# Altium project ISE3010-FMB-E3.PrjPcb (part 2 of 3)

## Sheet FPGA Power.SchDoc: FPGA Power
size 431 x 279 mm; Date: Not shown in title block; ApprovedBy: Not shown in title block; CheckedBy: Not shown in title block; Author: Not shown in title block; CompanyName: Not shown in title block; Engineer: Not shown in title block; Organization: Not shown in title block; Address1: Not shown in title block; Address2: Not shown in title block; Address3: Not shown in title block; Address4: Not shown in title block; DocumentNumber: 6; Revision: Use project parameter SCH_Rev; SheetNumber: 6; SheetTotal: 9; PageSetup: Record=PageOptions|CenterHorizontal=True|CenterVertical=True|PrintScale=1.00|XCorrection=1.00|YCorrection=1.00|PrintKind=0|BorderSize=5000000|LeftOffset=0|BottomOffset=0|Orientation=2|PaperLength=1000|PaperWidth=1000|Scale=100|PaperSource=15|PrintQuality=600|MediaType=1|DitherType=10|PaperKind=Letter|PrintScaleMode=1
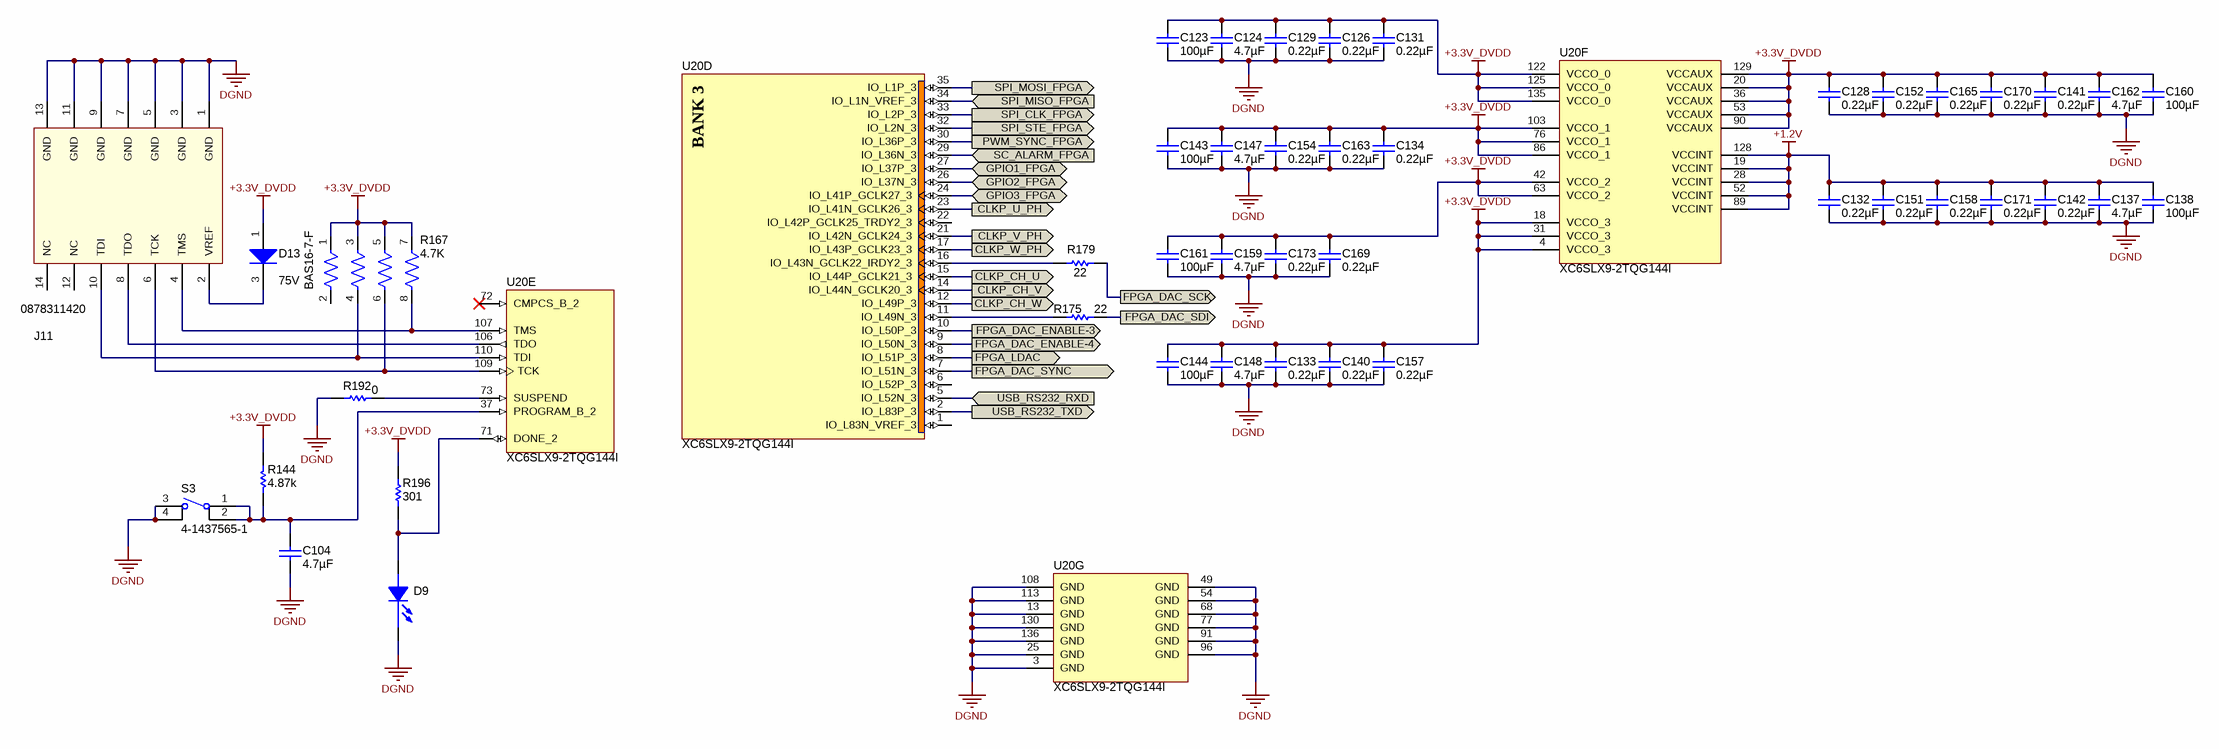
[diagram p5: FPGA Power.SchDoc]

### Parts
C104  ValueDisplayed: 4.7µF  [0603]  (hidden comment: C0603C475K9PACTU)
C123  ValueDisplayed: 100µF  [1206]  (hidden comment: GRM31CR60J107ME39L)
C124  ValueDisplayed: 4.7µF  [0603]  (hidden comment: C0603C475K9PACTU)
C126  ValueDisplayed: 0.22µF  [0603]  (hidden comment: GRM188R70J224KA88D)
C128  ValueDisplayed: 0.22µF  [0603]  (hidden comment: GRM188R70J224KA88D)
C129  ValueDisplayed: 0.22µF  [0603]  (hidden comment: GRM188R70J224KA88D)
C131  ValueDisplayed: 0.22µF  [0603]  (hidden comment: GRM188R70J224KA88D)
C132  ValueDisplayed: 0.22µF  [0603]  (hidden comment: GRM188R70J224KA88D)
C133  ValueDisplayed: 0.22µF  [0603]  (hidden comment: GRM188R70J224KA88D)
C134  ValueDisplayed: 0.22µF  [0603]  (hidden comment: GRM188R70J224KA88D)
C137  ValueDisplayed: 4.7µF  [0603]  (hidden comment: C0603C475K9PACTU)
C138  ValueDisplayed: 100µF  [1206]  (hidden comment: GRM31CR60J107ME39L)
C140  ValueDisplayed: 0.22µF  [0603]  (hidden comment: GRM188R70J224KA88D)
C141  ValueDisplayed: 0.22µF  [0603]  (hidden comment: GRM188R70J224KA88D)
C142  ValueDisplayed: 0.22µF  [0603]  (hidden comment: GRM188R70J224KA88D)
C143  ValueDisplayed: 100µF  [1206]  (hidden comment: GRM31CR60J107ME39L)
C144  ValueDisplayed: 100µF  [1206]  (hidden comment: GRM31CR60J107ME39L)
C147  ValueDisplayed: 4.7µF  [0603]  (hidden comment: C0603C475K9PACTU)
C148  ValueDisplayed: 4.7µF  [0603]  (hidden comment: C0603C475K9PACTU)
C151  ValueDisplayed: 0.22µF  [0603]  (hidden comment: GRM188R70J224KA88D)
C152  ValueDisplayed: 0.22µF  [0603]  (hidden comment: GRM188R70J224KA88D)
C154  ValueDisplayed: 0.22µF  [0603]  (hidden comment: GRM188R70J224KA88D)
C157  ValueDisplayed: 0.22µF  [0603]  (hidden comment: GRM188R70J224KA88D)
C158  ValueDisplayed: 0.22µF  [0603]  (hidden comment: GRM188R70J224KA88D)
C159  ValueDisplayed: 4.7µF  [0603]  (hidden comment: C0603C475K9PACTU)
C160  ValueDisplayed: 100µF  [1206]  (hidden comment: GRM31CR60J107ME39L)
C161  ValueDisplayed: 100µF  [1206]  (hidden comment: GRM31CR60J107ME39L)
C162  ValueDisplayed: 4.7µF  [0603]  (hidden comment: C0603C475K9PACTU)
C163  ValueDisplayed: 0.22µF  [0603]  (hidden comment: GRM188R70J224KA88D)
C165  ValueDisplayed: 0.22µF  [0603]  (hidden comment: GRM188R70J224KA88D)
C169  ValueDisplayed: 0.22µF  [0603]  (hidden comment: GRM188R70J224KA88D)
C170  ValueDisplayed: 0.22µF  [0603]  (hidden comment: GRM188R70J224KA88D)
C171  ValueDisplayed: 0.22µF  [0603]  (hidden comment: GRM188R70J224KA88D)
C173  ValueDisplayed: 0.22µF  [0603]  (hidden comment: GRM188R70J224KA88D)
D9  (no value)  [LED0603AA]
D13  BAS16-7-F  value 75V  [SOT-23]
J11  0878311420  [CONN_0878311420]
R144  value 4.87k  [0603]  (hidden comment: CRCW06034K87FKEA)
R167  4.7K  [R-ACAS_0612]
R175  value 22  [0402]  (hidden comment: CRCW040222R0JNED)
R179  value 22  [0402]  (hidden comment: CRCW040222R0JNED)
R192  value 0  [0603]  (hidden comment: CRCW06030000Z0EA)
R196  value 301  [0603]  (hidden comment: RT0603DRE07301RL)
S3  4-1437565-1  [SW_FSM4JSMA]
U20  XC6SLX9-2TQG144I  [TQG144_N]  (parts D,E,F,G of 7)

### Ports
CLKP_CH_U (out), CLKP_CH_V (out), CLKP_CH_W (out), CLKP_U_PH (out), CLKP_V_PH (out), CLKP_W_PH (out), FPGA_DAC_ENABLE-3 (out), FPGA_DAC_ENABLE-4 (out), FPGA_DAC_SCK (out), FPGA_DAC_SDI (out), FPGA_DAC_SYNC (out), FPGA_LDAC (out), GPIO1_FPGA (bidir), GPIO2_FPGA (bidir), GPIO3_FPGA (bidir), PWM_SYNC_FPGA, SC_ALARM_FPGA (in), SPI_CLK_FPGA, SPI_MISO_FPGA (in), SPI_MOSI_FPGA, SPI_STE_FPGA, USB_RS232_RXD (in), USB_RS232_TXD (out)

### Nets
+1.2V: C132.2 C137.1 C138.1 C142.2 C151.2 C158.2 C171.2 U20.19(VCCINT) U20.28(VCCINT) U20.52(VCCINT) U20.89(VCCINT) U20.128(VCCINT)
+3.3V_DVDD: C123.1 C124.1 C126.2 C128.2 C129.2 C131.2 C133.2 C134.2 C140.2 C141.2 C143.1 C144.1 C147.1 C148.1 C152.2 C154.2 C157.2 C159.1 C160.1 C161.1 C162.1 C163.2 C165.2 C169.2 C170.2 C173.2 D13.1(A) R144.2 R167.1 R167.3 R167.5 R167.7 R196.2 U20.4(VCCO_3) U20.18(VCCO_3) U20.20(VCCAUX) U20.31(VCCO_3) U20.36(VCCAUX) U20.42(VCCO_2) U20.53(VCCAUX) U20.63(VCCO_2) U20.76(VCCO_1) U20.86(VCCO_1) U20.90(VCCAUX) U20.103(VCCO_1) U20.122(VCCO_0) U20.125(VCCO_0) U20.129(VCCAUX) U20.135(VCCO_0)
DGND: C104.1 C123.2 C124.2 C126.1 C128.1 C129.1 C131.1 C132.1 C133.1 C134.1 C137.2 C138.2 C140.1 C141.1 C142.1 C143.2 C144.2 C147.2 C148.2 C151.1 C152.1 C154.1 C157.1 C158.1 C159.2 C160.2 C161.2 C162.2 C163.1 C165.1 C169.1 C170.1 C171.1 C173.1 D9.1(C) J11.1(GND) J11.3(GND) J11.5(GND) J11.7(GND) J11.9(GND) J11.11(GND) J11.13(GND) R192.1 S3.3 S3.4 U20.3(GND) U20.13(GND) U20.25(GND) U20.49(GND) U20.54(GND) U20.68(GND) U20.77(GND) U20.91(GND) U20.96(GND) U20.108(GND) U20.113(GND) U20.130(GND) U20.136(GND)
CLKP_CH_U: U20.15(IO_L44P_GCLK21_3) ; port CLKP_CH_U
CLKP_CH_V: U20.14(IO_L44N_GCLK20_3) ; port CLKP_CH_V
CLKP_CH_W: U20.12(IO_L49P_3) ; port CLKP_CH_W
CLKP_U_PH: U20.23(IO_L41N_GCLK26_3) ; port CLKP_U_PH
CLKP_V_PH: U20.21(IO_L42N_GCLK24_3) ; port CLKP_V_PH
CLKP_W_PH: U20.17(IO_L43P_GCLK23_3) ; port CLKP_W_PH
FPGA_DAC_ENABLE-3: U20.10(IO_L50P_3) ; port FPGA_DAC_ENABLE-3
FPGA_DAC_ENABLE-4: U20.9(IO_L50N_3) ; port FPGA_DAC_ENABLE-4
FPGA_DAC_SCK: R179.1 ; port FPGA_DAC_SCK
FPGA_DAC_SDI: R175.1 ; port FPGA_DAC_SDI
FPGA_DAC_SYNC: U20.7(IO_L51N_3) ; port FPGA_DAC_SYNC
FPGA_LDAC: U20.8(IO_L51P_3) ; port FPGA_LDAC
GPIO1_FPGA: U20.27(IO_L37P_3) ; port GPIO1_FPGA
GPIO2_FPGA: U20.26(IO_L37N_3) ; port GPIO2_FPGA
GPIO3_FPGA: U20.24(IO_L41P_GCLK27_3) ; port GPIO3_FPGA
PWM_SYNC_FPGA: U20.30(IO_L36P_3) ; port PWM_SYNC_FPGA
SC_ALARM_FPGA: U20.29(IO_L36N_3) ; port SC_ALARM_FPGA
SPI_CLK_FPGA: U20.33(IO_L2P_3) ; port SPI_CLK_FPGA
SPI_MISO_FPGA: U20.34(IO_L1N_VREF_3) ; port SPI_MISO_FPGA
SPI_MOSI_FPGA: U20.35(IO_L1P_3) ; port SPI_MOSI_FPGA
SPI_STE_FPGA: U20.32(IO_L2N_3) ; port SPI_STE_FPGA
USB_RS232_RXD: U20.5(IO_L52N_3) ; port USB_RS232_RXD
USB_RS232_TXD: U20.2(IO_L83P_3) ; port USB_RS232_TXD
NetC104_2: C104.2 R144.1 S3.1 S3.2 U20.37(PROGRAM_B_2)
NetD9_2: D9.2(A) R196.1 U20.71(DONE_2)
NetD13_3: D13.3(K) J11.2(VREF)
NetJ11_4: J11.4(TMS) R167.8 U20.107(TMS)
NetJ11_6: J11.6(TCK) R167.6 U20.109(TCK)
NetJ11_8: J11.8(TDO) U20.106(TDO)
NetJ11_10: J11.10(TDI) R167.4 U20.110(TDI)
NetR175_2: R175.2 U20.11(IO_L49N_3)
NetR179_2: R179.2 U20.16(IO_L43N_GCLK22_IRDY2_3)
NetR192_2: R192.2 U20.73(SUSPEND)

Not connected (* = marked no-connect by the designer): J11 12(NC) 14(NC); R167 2; U20 1(IO_L83N_VREF_3) 6(IO_L52P_3) 22(IO_L42P_GCLK25_TRDY2_3) 72(CMPCS_B_2)*

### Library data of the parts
C104 C124 C137 C147 C148 C159 C162 = C0603C475K9PACTU: CAP, CERM, 4.7uF, 6.3V, +/-10%, X5R, 0603; Manufacturer: Kemet; Polarized: N; CompType: Capacitor; U/M: EA; Cap_F: 0.0000047; Tolerance_%: 10; ESR_Ohm: 0.006; Value1: 0.006 ohm; VDC_V: 6.3; IRMS_A: 7.24; TaMin_C: -55; TaMax_C: 85
C123 C138 C143 C144 C160 C161 = GRM31CR60J107ME39L: CAP, CERM, 100uF, 6.3V, +/-20%, X5R, 1206; Manufacturer: MuRata; Polarized: N; CompType: Capacitor; U/M: EA; Cap_F: 0.0001; Tolerance_%: 20; ESR_Ohm: 0.003; Value1: 0.003 ohm; VDC_V: 6.3; TaMin_C: -55; TaMax_C: 85
C126 C128 C129 C131-C134 C140-C142 C151 C152 C154 C157 C158 C163 C165 C169-C171 C173 = GRM188R70J224KA88D: CAP, CERM, 0.22uF, 6.3V, +/-10%, X7R, 0603; Manufacturer: MuRata; Polarized: N; CompType: Capacitor; U/M: EA; Cap_F: 0.00000022; Tolerance_%: 10; Value1: Unknown; VDC_V: 6.3; TaMin_C: -55; TaMax_C: 125
D9 = LED_LG L29K-G2J1-24-Z: LED SmartLED Green 570NM; Manufacturer: OSRAM; SymbolCreator: x0120606
D13 = BAS16-7-F: Diode, Ultrafast, 75V, 0.3A, SOT-23; Manufacturer: Diodes Inc.; U/M: EA; Vf_V: 1.125; Value2: 1.125V; Io_A: 0.3; Vr_V: 75
J11 = CON_0878311420: Cnnector Header 14Pos 2mm Vert Gold; Manufacturer: Molex Inc; SymbolCreator: x0120606
R144 = CRCW06034K87FKEA: RES, 4.87k ohm, 1%, 0.1W, 0603; Manufacturer: Vishay-Dale; CompType: Resistor; Res_ohm: 4870; Value_Code: 4k87; Tolerance_%: 1; Power_W: 0.1; VDC_V: 75; TempCo: 100 ppm/C; EIA_Code: E96; U/M: EA
R167 = R-ACAS0612_SERIES: Resistor, Chip Array, 4.7K OHM 4 RES 0612; Manufacturer: Vishay; PartNumber: ACASA470124701P100; Area: 22308
R175 R179 = CRCW040222R0JNED: RES, 22 ohm, 5%, 0.063W, 0402; Manufacturer: Vishay-Dale; CompType: Resistor; Value_Code: 22R0; Tolerance_%: 5; Power_W: 0.063; VDC_V: 50; TempCo: 200 ppm/C; EIA_Code: E24; U/M: EA
R192 = CRCW06030000Z0EA: RES, 0 ohm, 5%, 0.1W, 0603; Manufacturer: Vishay-Dale; CompType: Resistor; Value_Code: 0000; Tolerance_%: 5; Power_W: 0.1; VDC_V: 75; TempCo: 200 ppm/C; EIA_Code: E24; U/M: EA
R196 = RT0603DRE07301RL: RES, 301 ohm, 0.5%, 0.1W, 0603; Manufacturer: Yageo America; CompType: Resistor; Value_Code: 301R; Tolerance_%: 0.5; Power_W: 0.1; VDC_V: 75; TempCo: 50 ppm/C; EIA_Code: E192; U/M: EA
S3 = 4-1437565-1: Switch, Tactile, SPST-NO, 0.05A, 12V, SMT; Manufacturer: TE Connectivity; SymbolCreator: a0412235; VDC_V: 12; SwitchFunction: Off-Mom; PositionCount: 1; CurrentRating_mA: 50
U20 = XC6SLX9-2TQG144I: IC FPGA SPARTAN, 102 I/O, 144TQFP; Manufacturer: Xilinx; SymbolCreator: x0120606

## Sheet FPGA CLOCK_USB.SchDoc: FPGA CLOCK_USB
size 431 x 279 mm; Date: Not shown in title block; ApprovedBy: Not shown in title block; CheckedBy: Not shown in title block; Author: Not shown in title block; CompanyName: Not shown in title block; Engineer: Not shown in title block; Organization: Not shown in title block; Address1: Not shown in title block; Address2: Not shown in title block; Address3: Not shown in title block; Address4: Not shown in title block; DocumentNumber: 7; Revision: Use project parameter SCH_Rev; SheetNumber: 7; SheetTotal: 9; PageSetup: Record=PageOptions|CenterHorizontal=True|CenterVertical=True|PrintScale=0.62|XCorrection=1.00|YCorrection=1.00|PrintKind=0|BorderSize=5000000|LeftOffset=0|BottomOffset=0|Orientation=2|PaperLength=1000|PaperWidth=1000|Scale=100|PaperSource=15|PrintQuality=600|MediaType=1|DitherType=10|PaperKind=Letter|PrintScaleMode=1
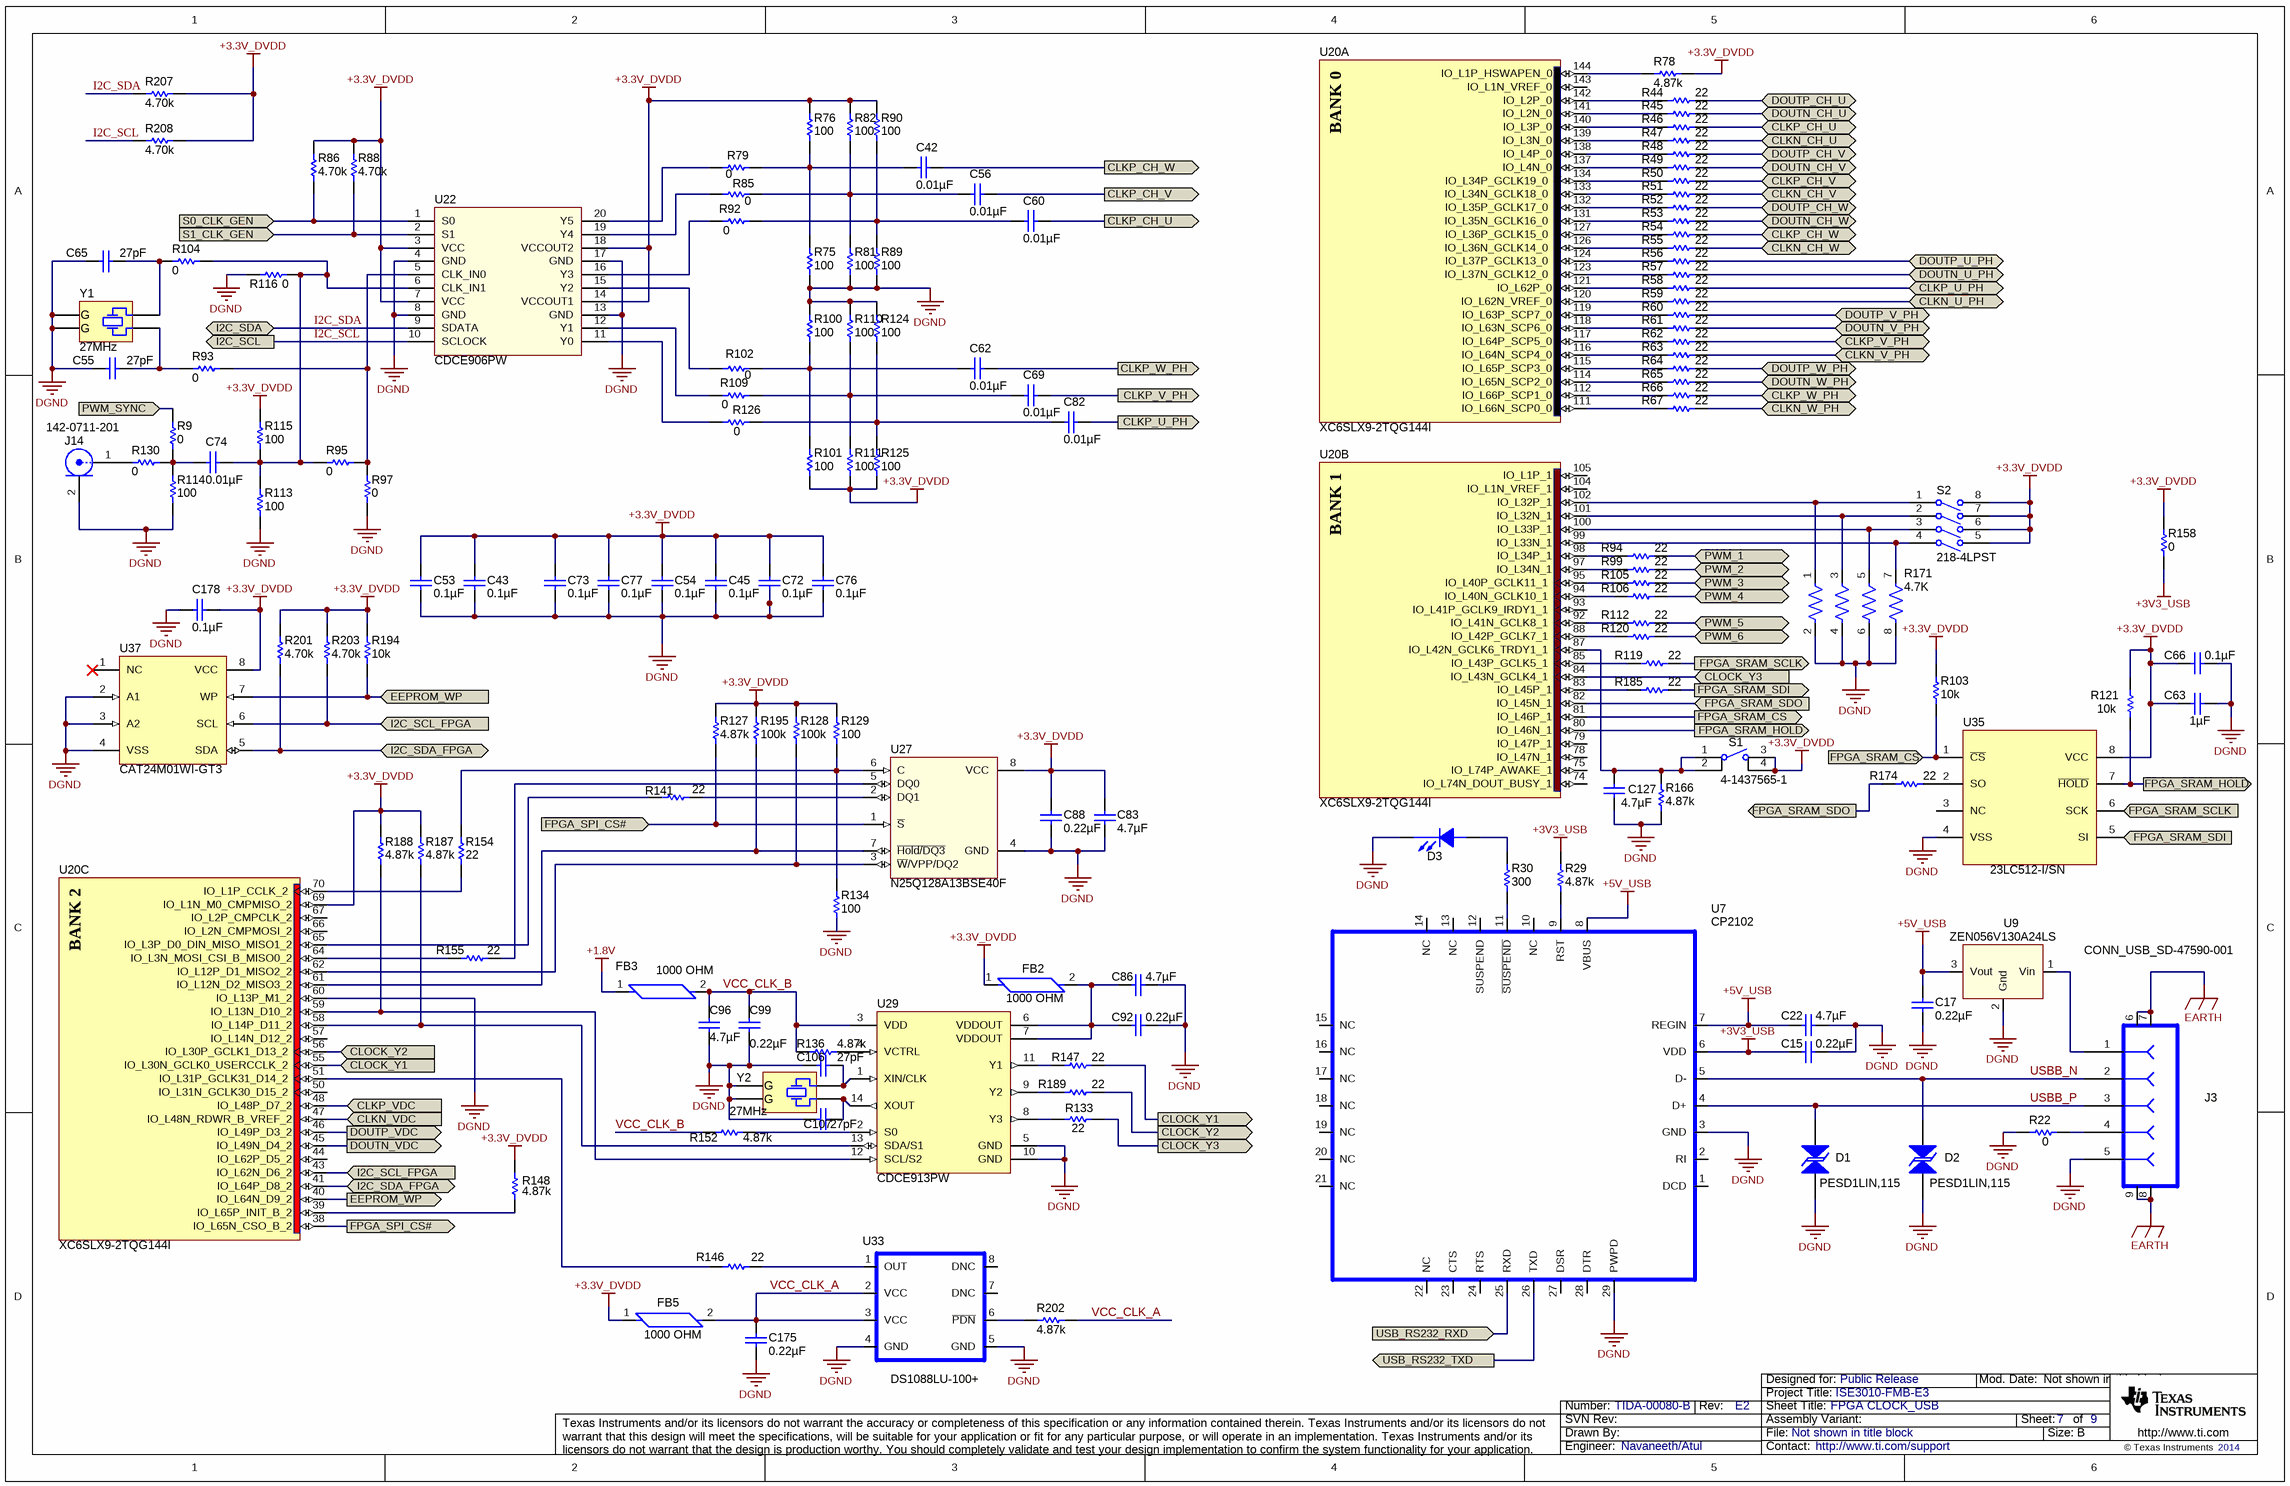
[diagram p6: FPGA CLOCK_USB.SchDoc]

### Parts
C15  ValueDisplayed: 0.22µF  [0603]  (hidden comment: GRM188R70J224KA88D)
C17  ValueDisplayed: 0.22µF  [0603]  (hidden comment: GRM188R70J224KA88D)
C22  ValueDisplayed: 4.7µF  [0603]  (hidden comment: C0603C475K9PACTU)
C42  ValueDisplayed: 0.01µF  [0603]  (hidden comment: 06031C103KAT2A)
C43  ValueDisplayed: 0.1µF  [0603]  (hidden comment: 06033C104JAT2A)
C45  ValueDisplayed: 0.1µF  [0603]  (hidden comment: 06033C104JAT2A)
C53  ValueDisplayed: 0.1µF  [0603]  (hidden comment: 06033C104JAT2A)
C54  ValueDisplayed: 0.1µF  [0603]  (hidden comment: 06033C104JAT2A)
C55  ValueDisplayed: 27pF  [0603]  (hidden comment: 06035A270JAT2A)
C56  ValueDisplayed: 0.01µF  [0603]  (hidden comment: 06031C103KAT2A)
C60  ValueDisplayed: 0.01µF  [0603]  (hidden comment: 06031C103KAT2A)
C62  ValueDisplayed: 0.01µF  [0603]  (hidden comment: 06031C103KAT2A)
C63  ValueDisplayed: 1µF  [0603]  (hidden comment: C1608X5R1C105K)
C65  ValueDisplayed: 27pF  [0603]  (hidden comment: 06035A270JAT2A)
C66  ValueDisplayed: 0.1µF  [0603]  (hidden comment: 0603YC104JAT2A)
C69  ValueDisplayed: 0.01µF  [0603]  (hidden comment: 06031C103KAT2A)
C72  ValueDisplayed: 0.1µF  [0603]  (hidden comment: 06033C104JAT2A)
C73  ValueDisplayed: 0.1µF  [0603]  (hidden comment: 06033C104JAT2A)
C74  ValueDisplayed: 0.01µF  [0603]  (hidden comment: 06031C103KAT2A)
C76  ValueDisplayed: 0.1µF  [0603]  (hidden comment: 06033C104JAT2A)
C77  ValueDisplayed: 0.1µF  [0603]  (hidden comment: 06033C104JAT2A)
C82  ValueDisplayed: 0.01µF  [0603]  (hidden comment: 06031C103KAT2A)
C83  ValueDisplayed: 4.7µF  [0603]  (hidden comment: C0603C475K9PACTU)
C86  ValueDisplayed: 4.7µF  [0603]  (hidden comment: C0603C475K9PACTU)
C88  ValueDisplayed: 0.22µF  [0603]  (hidden comment: GRM188R70J224KA88D)
C92  ValueDisplayed: 0.22µF  [0603]  (hidden comment: GRM188R70J224KA88D)
C96  ValueDisplayed: 4.7µF  [0603]  (hidden comment: C0603C475K9PACTU)
C99  ValueDisplayed: 0.22µF  [0603]  (hidden comment: GRM188R70J224KA88D)
C106  ValueDisplayed: 27pF  [0603]  (hidden comment: 06035A270JAT2A)
C107  ValueDisplayed: 27pF  [0603]  (hidden comment: 06035A270JAT2A)
C127  ValueDisplayed: 4.7µF  [0603]  (hidden comment: C0603C475K9PACTU)
C175  ValueDisplayed: 0.22µF  [0603]  (hidden comment: GRM188R70J224KA88D)
C178  ValueDisplayed: 0.1µF  [0603]  (hidden comment: 0603YC104JAT2A)
D1  PESD1LIN,115  [sod-323]
D2  PESD1LIN,115  [sod-323]
D3  (no value)  [LED0603AA]
FB2  value 1000 OHM  [FB0603]
FB3  value 1000 OHM  [FB0603]
FB5  value 1000 OHM  [FB0603]
J3  CONN_USB_SD-47590-001  [USB-SD-47590-001]
J14  142-0711-201  [142-0711-201]
R9  value 0  [0603]  (hidden comment: CRCW06030000Z0EA)
R22  value 0  [0603]  (hidden comment: CRCW06030000Z0EA)
R29  value 4.87k  [0603]  (hidden comment: CRCW06034K87FKEA)
R30  value 300  [0603]  (hidden comment: CRCW0603300RJNEA)
R44  value 22  [0402]  (hidden comment: CRCW040222R0JNED)
R45  value 22  [0402]  (hidden comment: CRCW040222R0JNED)
R46  value 22  [0402]  (hidden comment: CRCW040222R0JNED)
R47  value 22  [0402]  (hidden comment: CRCW040222R0JNED)
R48  value 22  [0402]  (hidden comment: CRCW040222R0JNED)
R49  value 22  [0402]  (hidden comment: CRCW040222R0JNED)
R50  value 22  [0402]  (hidden comment: CRCW040222R0JNED)
R51  value 22  [0402]  (hidden comment: CRCW040222R0JNED)
R52  value 22  [0402]  (hidden comment: CRCW040222R0JNED)
R53  value 22  [0402]  (hidden comment: CRCW040222R0JNED)
R54  value 22  [0402]  (hidden comment: CRCW040222R0JNED)
R55  value 22  [0402]  (hidden comment: CRCW040222R0JNED)
R56  value 22  [0402]  (hidden comment: CRCW040222R0JNED)
R57  value 22  [0402]  (hidden comment: CRCW040222R0JNED)
R58  value 22  [0402]  (hidden comment: CRCW040222R0JNED)
R59  value 22  [0402]  (hidden comment: CRCW040222R0JNED)
R60  value 22  [0402]  (hidden comment: CRCW040222R0JNED)
R61  value 22  [0402]  (hidden comment: CRCW040222R0JNED)
R62  value 22  [0402]  (hidden comment: CRCW040222R0JNED)
R63  value 22  [0402]  (hidden comment: CRCW040222R0JNED)
R64  value 22  [0402]  (hidden comment: CRCW040222R0JNED)
R65  value 22  [0402]  (hidden comment: CRCW040222R0JNED)
R66  value 22  [0402]  (hidden comment: CRCW040222R0JNED)
R67  value 22  [0402]  (hidden comment: CRCW040222R0JNED)
R75  value 100  [0603]  (hidden comment: CRCW0603100RJNEA)
R76  value 100  [0603]  (hidden comment: CRCW0603100RJNEA)
R78  value 4.87k  [0603]  (hidden comment: CRCW06034K87FKEA)
R79  value 0  [0603]  (hidden comment: CRCW06030000Z0EA)
R81  value 100  [0603]  (hidden comment: CRCW0603100RJNEA)
R82  value 100  [0603]  (hidden comment: CRCW0603100RJNEA)
R85  value 0  [0603]  (hidden comment: CRCW06030000Z0EA)
R86  value 4.70k  [0603]  (hidden comment: RC0603FR-074K7L)
R88  value 4.70k  [0603]  (hidden comment: RC0603FR-074K7L)
R89  value 100  [0603]  (hidden comment: CRCW0603100RJNEA)
R90  value 100  [0603]  (hidden comment: CRCW0603100RJNEA)
R92  value 0  [0603]  (hidden comment: CRCW06030000Z0EA)
R93  value 0  [0402]  (hidden comment: CRCW04020000Z0ED)
R94  value 22  [0402]  (hidden comment: CRCW040222R0JNED)
R95  value 0  [0402]  (hidden comment: CRCW04020000Z0ED)
R97  value 0  [0402]  (hidden comment: CRCW04020000Z0ED)
R99  value 22  [0402]  (hidden comment: CRCW040222R0JNED)
R100  value 100  [0603]  (hidden comment: CRCW0603100RJNEA)
R101  value 100  [0603]  (hidden comment: CRCW0603100RJNEA)
R102  value 0  [0603]  (hidden comment: CRCW06030000Z0EA)
R103  value 10k  [0603]  (hidden comment: CRCW060310K0JNEA)
R104  value 0  [0402]  (hidden comment: CRCW04020000Z0ED)
R105  value 22  [0402]  (hidden comment: CRCW040222R0JNED)
R106  value 22  [0402]  (hidden comment: CRCW040222R0JNED)
R109  value 0  [0603]  (hidden comment: CRCW06030000Z0EA)
R110  value 100  [0603]  (hidden comment: CRCW0603100RJNEA)
R111  value 100  [0603]  (hidden comment: CRCW0603100RJNEA)
R112  value 22  [0402]  (hidden comment: CRCW040222R0JNED)
R113  value 100  [0603]  (hidden comment: CRCW0603100RJNEA)
R114  value 100  [0603]  (hidden comment: CRCW0603100RJNEA)
R115  value 100  [0603]  (hidden comment: CRCW0603100RJNEA)
R116  value 0  [0402]  (hidden comment: CRCW04020000Z0ED)
R119  value 22  [0402]  (hidden comment: CRCW040222R0JNED)
R120  value 22  [0402]  (hidden comment: CRCW040222R0JNED)
R121  value 10k  [0603]  (hidden comment: CRCW060310K0JNEA)
R124  value 100  [0603]  (hidden comment: CRCW0603100RJNEA)
R125  value 100  [0603]  (hidden comment: CRCW0603100RJNEA)
R126  value 0  [0603]  (hidden comment: CRCW06030000Z0EA)
R127  value 4.87k  [0603]  (hidden comment: CRCW06034K87FKEA)
R128  value 100k  [0603]  (hidden comment: CRCW0603100KFKEA)
R129  value 100  [0603]  (hidden comment: CRCW0603100RJNEA)
R130  value 0  [0603]  (hidden comment: CRCW06030000Z0EA)
R133  value 22  [0402]  (hidden comment: CRCW040222R0JNED)
R134  value 100  [0603]  (hidden comment: CRCW0603100RJNEA)
R136  value 4.87k  [0603]  (hidden comment: CRCW06034K87FKEA)
R141  value 22  [0402]  (hidden comment: CRCW040222R0JNED)
R146  value 22  [0402]  (hidden comment: CRCW040222R0JNED)
R147  value 22  [0402]  (hidden comment: CRCW040222R0JNED)
R148  value 4.87k  [0603]  (hidden comment: CRCW06034K87FKEA)
R152  value 4.87k  [0603]  (hidden comment: CRCW06034K87FKEA)
R154  value 22  [0402]  (hidden comment: CRCW040222R0JNED)
R155  value 22  [0402]  (hidden comment: CRCW040222R0JNED)
R158  value 0  [0603]  (hidden comment: CRCW06030000Z0EA)
R166  value 4.87k  [0603]  (hidden comment: CRCW06034K87FKEA)
R171  4.7K  [R-ACAS_0612]
R174  value 22  [0402]  (hidden comment: CRCW040222R0JNED)
R185  value 22  [0402]  (hidden comment: CRCW040222R0JNED)
R187  value 4.87k  [0603]  (hidden comment: CRCW06034K87FKEA)
R188  value 4.87k  [0603]  (hidden comment: CRCW06034K87FKEA)
R189  value 22  [0402]  (hidden comment: CRCW040222R0JNED)
R194  value 10k  [0603]  (hidden comment: RC0603JR-0710KL)
R195  value 100k  [0603]  (hidden comment: CRCW0603100KFKEA)
R201  value 4.70k  [0603]  (hidden comment: RC0603FR-074K7L)
R202  value 4.87k  [0603]  (hidden comment: CRCW06034K87FKEA)
R203  value 4.70k  [0603]  (hidden comment: RC0603FR-074K7L)
R207  value 4.70k  [0603]  (hidden comment: RC0603FR-074K7L)
R208  value 4.70k  [0603]  (hidden comment: RC0603FR-074K7L)
S1  4-1437565-1  [SW_FSM4JSMA]
S2  218-4LPST  [SW_218-4LPST]
U7  CP2102  [QFN28[RHD]]
U9  ZEN056V130A24LS  [POLYZEN 4 x 4 SMD]
U20  XC6SLX9-2TQG144I  [TQG144_N]  (parts A,B,C of 7)
U22  CDCE906PW  [PW0020A_L]
U27  N25Q128A13BSE40F  [SO8W]
U29  CDCE913PW  [PW0014A_N]
U33  DS1088LU-100+  [DGK8]
U35  23LC512-I/SN  [SO8]
U37  CAT24M01WI-GT3  [SO8]
Y1  Frequency: 27MHz  [XTAL_TXC-7B]  (hidden comment: 7B-27.000MEEQ-T)
Y2  Frequency: 27MHz  [XTAL_TXC-7B]  (hidden comment: 7B-27.000MEEQ-T)

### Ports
CLKN_CH_U (bidir), CLKN_CH_V (bidir), CLKN_CH_W (bidir), CLKN_U_PH (bidir), CLKN_V_PH (bidir), CLKN_VDC (in), CLKN_W_PH (bidir), CLKP_CH_U (bidir), CLKP_CH_U (out), CLKP_CH_V (bidir), CLKP_CH_V (out), CLKP_CH_W (bidir), CLKP_CH_W (out), CLKP_U_PH (bidir), CLKP_U_PH (out), CLKP_V_PH (bidir), CLKP_V_PH (out), CLKP_VDC (in), CLKP_W_PH (bidir), CLKP_W_PH (out), CLOCK_Y1 (in), CLOCK_Y1 (out), CLOCK_Y2 (in), CLOCK_Y2 (out), CLOCK_Y3 (in), CLOCK_Y3 (out), DOUTN_CH_U (bidir), DOUTN_CH_V (bidir), DOUTN_CH_W (bidir), DOUTN_U_PH (bidir), DOUTN_V_PH (bidir), DOUTN_VDC (out), DOUTN_W_PH (bidir), DOUTP_CH_U (bidir), DOUTP_CH_V (bidir), DOUTP_CH_W (bidir), DOUTP_U_PH (bidir), DOUTP_V_PH (bidir), DOUTP_VDC (out), DOUTP_W_PH (bidir), EEPROM_WP (in), EEPROM_WP (out), FPGA_SPI_CS# (in), FPGA_SPI_CS# (out), FPGA_SRAM_CS (in), FPGA_SRAM_CS (out), FPGA_SRAM_HOLD (out), FPGA_SRAM_SCLK (in), FPGA_SRAM_SCLK (out), FPGA_SRAM_SDI (in), FPGA_SRAM_SDI (out), FPGA_SRAM_SDO (in), FPGA_SRAM_SDO (out), I2C_SCL, I2C_SCL_FPGA, I2C_SDA (bidir), I2C_SDA_FPGA (bidir), PWM_1 (bidir), PWM_2 (bidir), PWM_3 (bidir), PWM_4 (bidir), PWM_5 (bidir), PWM_6 (bidir), PWM_SYNC (in), S0_CLK_GEN (in), S1_CLK_GEN (in), USB_RS232_RXD (in), USB_RS232_TXD (out)

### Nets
+1.8V: FB3.1
+3.3V_DVDD: C43.1 C45.1 C53.1 C54.1 C63.1 C66.1 C72.1 C73.1 C76.1 C77.1 C83.2 C88.2 C178.1 FB2.1 FB5.1 R76.2 R78.2 R82.2 R86.2 R88.2 R90.2 R101.1 R103.2 R111.1 R115.2 R121.2 R125.1 R127.1 R128.1 R129.2 R148.2 R158.2 R187.2 R188.2 R194.2 R195.1 R201.2 R203.2 R207.1 R208.1 S1.3 S1.4 S2.5(B4) S2.6(B3) S2.7(B2) S2.8(B1) U20.69(IO_L1N_M0_CMPMISO_2) U22.3(VCC) U22.7(VCC) U22.14(VCCOUT1) U22.18(VCCOUT2) U27.8(VCC) U35.8(VCC) U37.8(VCC)
+3V3_USB: C15.1 R29.2 R158.1 U7.6(VDD)
+5V_USB: C17.1 C22.1 U7.7(REGIN) U7.8(VBUS) U9.3(Vout)
DGND: C15.2 C17.2 C22.2 C43.2 C45.2 C53.2 C54.2 C55.2 C63.2 C65.2 C66.2 C72.2 C73.2 C76.2 C77.2 C83.1 C86.1 C88.1 C92.1 C96.1 C99.1 C106.2 C107.2 C127.1 C175.1 C178.2 D1.1 D2.1 D3.1(C) J3.5 J14.2 R22.1 R75.1 R81.1 R89.1 R97.1 R100.2 R110.2 R113.1 R114.1 R116.1 R124.2 R134.1 R166.2 R171.2 R171.4 R171.6 R171.8 U7.3(GND) U7.29(PWPD) U9.2(Gnd) U20.60(IO_L13P_M1_2) U22.4(GND) U22.8(GND) U22.13(GND) U22.17(GND) U27.4(GND) U29.5(GND) U29.10(GND) U33.4(GND) U33.5(GND) U35.4(VSS) U37.2(A1) U37.3(A2) U37.4(VSS) Y1.2(GND) Y1.4(GND) Y2.2(GND) Y2.4(GND)
EARTH: J3.6 J3.7 J3.8 J3.9
CLKN_CH_U: R47.1 ; port CLKN_CH_U
CLKN_CH_V: R51.1 ; port CLKN_CH_V
CLKN_CH_W: R55.1 ; port CLKN_CH_W
CLKN_U_PH: R59.1 ; port CLKN_U_PH
CLKN_V_PH: R63.1 ; port CLKN_V_PH
CLKN_VDC: U20.47(IO_L48N_RDWR_B_VREF_2) ; port CLKN_VDC
CLKN_W_PH: R67.1 ; port CLKN_W_PH
CLKP_CH_U: C60.1 R46.1 ; port CLKP_CH_U
CLKP_CH_V: C56.1 R50.1 ; port CLKP_CH_V
CLKP_CH_W: C42.1 R54.1 ; port CLKP_CH_W
CLKP_U_PH: C82.1 R58.1 ; port CLKP_U_PH
CLKP_V_PH: C69.1 R62.1 ; port CLKP_V_PH
CLKP_VDC: U20.48(IO_L48P_D7_2) ; port CLKP_VDC
CLKP_W_PH: C62.1 R66.1 ; port CLKP_W_PH
CLOCK_Y1: R147.2 U20.55(IO_L30N_GCLK0_USERCCLK_2) ; port CLOCK_Y1
CLOCK_Y2: R189.2 U20.56(IO_L30P_GCLK1_D13_2) ; port CLOCK_Y2
CLOCK_Y3: R133.2 U20.84(IO_L43N_GCLK4_1) ; port CLOCK_Y3
DOUTN_CH_U: R45.1 ; port DOUTN_CH_U
DOUTN_CH_V: R49.1 ; port DOUTN_CH_V
DOUTN_CH_W: R53.1 ; port DOUTN_CH_W
DOUTN_U_PH: R57.1 ; port DOUTN_U_PH
DOUTN_V_PH: R61.1 ; port DOUTN_V_PH
DOUTN_VDC: U20.45(IO_L49N_D4_2) ; port DOUTN_VDC
DOUTN_W_PH: R65.1 ; port DOUTN_W_PH
DOUTP_CH_U: R44.1 ; port DOUTP_CH_U
DOUTP_CH_V: R48.1 ; port DOUTP_CH_V
DOUTP_CH_W: R52.1 ; port DOUTP_CH_W
DOUTP_U_PH: R56.1 ; port DOUTP_U_PH
DOUTP_V_PH: R60.1 ; port DOUTP_V_PH
DOUTP_VDC: U20.46(IO_L49P_D3_2) ; port DOUTP_VDC
DOUTP_W_PH: R64.1 ; port DOUTP_W_PH
EEPROM_WP: R194.1 U20.40(IO_L64N_D9_2) U37.7(WP) ; port EEPROM_WP
FPGA_SPI_CS#: R127.2 U20.38(IO_L65N_CSO_B_2) U27.1(~{S}) ; port FPGA_SPI_CS#
FPGA_SRAM_CS: R103.1 U20.81(IO_L46P_1) U35.1(~{CS}) ; port FPGA_SRAM_CS
FPGA_SRAM_HOLD: R121.1 U20.80(IO_L46N_1) U35.7(~{HOLD}) ; port FPGA_SRAM_HOLD
FPGA_SRAM_SCLK: R119.1 U35.6(SCK) ; port FPGA_SRAM_SCLK
FPGA_SRAM_SDI: R185.1 U35.5(SI) ; port FPGA_SRAM_SDI
FPGA_SRAM_SDO: R174.2 U20.82(IO_L45N_1) ; port FPGA_SRAM_SDO
I2C_SCL: R208.2 U22.10(SCLOCK) ; port I2C_SCL
I2C_SCL_FPGA: R203.1 U20.43(IO_L62N_D6_2) U37.6(SCL) ; port I2C_SCL_FPGA
I2C_SDA: R207.2 U22.9(SDATA) ; port I2C_SDA
I2C_SDA_FPGA: R201.1 U20.41(IO_L64P_D8_2) U37.5(SDA) ; port I2C_SDA_FPGA
PWM_1: R94.1 ; port PWM_1
PWM_2: R99.1 ; port PWM_2
PWM_3: R105.1 ; port PWM_3
PWM_4: R106.1 ; port PWM_4
PWM_5: R112.1 ; port PWM_5
PWM_6: R120.1 ; port PWM_6
PWM_SYNC: R9.2 ; port PWM_SYNC
S0_CLK_GEN: R86.1 U22.1(S0) ; port S0_CLK_GEN
S1_CLK_GEN: R88.1 U22.2(S1) ; port S1_CLK_GEN
USB_RS232_RXD: U7.25(RXD) ; port USB_RS232_RXD
USB_RS232_TXD: U7.26(TXD) ; port USB_RS232_TXD
USBB_N: D2.2 J3.2 U7.5(D-)
USBB_P: D1.2 J3.3 U7.4(D+)
VCC_CLK_A: C175.2 FB5.2 R202.1 U33.2(VCC) U33.3(VCC)
VCC_CLK_B: C96.2 C99.2 FB3.2 R136.2 R152.2 U29.3(VDD)
NetC42_2: C42.2 R75.2 R76.1 R79.2
NetC55_1: C55.1 R93.1 Y1.3
NetC56_2: C56.2 R81.2 R82.1 R85.2
NetC60_2: C60.2 R89.2 R90.1 R92.2
NetC62_2: C62.2 R100.1 R101.2 R102.2
NetC65_1: C65.1 R104.1 Y1.1
NetC69_2: C69.2 R109.2 R110.1 R111.2
NetC74_1: C74.1 R95.1 R104.2 R113.2 R115.1 R116.2 U22.6(CLK_IN1)
NetC74_2: C74.2 R9.1 R114.2 R130.2
NetC82_2: C82.2 R124.1 R125.2 R126.2
NetC86_2: C86.2 C92.2 FB2.2 U29.6(VDDOUT) U29.7(VDDOUT)
NetC106_1: C106.1 U29.1(XIN/CLK) Y2.1
NetC107_1: C107.1 U29.14(XOUT) Y2.3
NetC127_2: C127.2 R166.1 S1.1 S1.2 U20.87(IO_L42N_GCLK6_TRDY1_1)
NetD3_2: D3.2(A) R30.2
NetJ3_1: J3.1 U9.1(Vin)
NetJ3_4: J3.4 R22.2
NetJ14_1: J14.1 R130.1
NetR29_1: R29.1 U7.9(RST)
NetR30_1: R30.1 U7.11(~{SUSPEND})
NetR44_2: R44.2 U20.142(IO_L2P_0)
NetR45_2: R45.2 U20.141(IO_L2N_0)
NetR46_2: R46.2 U20.140(IO_L3P_0)
NetR47_2: R47.2 U20.139(IO_L3N_0)
NetR48_2: R48.2 U20.138(IO_L4P_0)
NetR49_2: R49.2 U20.137(IO_L4N_0)
NetR50_2: R50.2 U20.134(IO_L34P_GCLK19_0)
NetR51_2: R51.2 U20.133(IO_L34N_GCLK18_0)
NetR52_2: R52.2 U20.132(IO_L35P_GCLK17_0)
NetR53_2: R53.2 U20.131(IO_L35N_GCLK16_0)
NetR54_2: R54.2 U20.127(IO_L36P_GCLK15_0)
NetR55_2: R55.2 U20.126(IO_L36N_GCLK14_0)
NetR56_2: R56.2 U20.124(IO_L37P_GCLK13_0)
NetR57_2: R57.2 U20.123(IO_L37N_GCLK12_0)
NetR58_2: R58.2 U20.121(IO_L62P_0)
NetR59_2: R59.2 U20.120(IO_L62N_VREF_0)
NetR60_2: R60.2 U20.119(IO_L63P_SCP7_0)
NetR61_2: R61.2 U20.118(IO_L63N_SCP6_0)
NetR62_2: R62.2 U20.117(IO_L64P_SCP5_0)
NetR63_2: R63.2 U20.116(IO_L64N_SCP4_0)
NetR64_2: R64.2 U20.115(IO_L65P_SCP3_0)
NetR65_2: R65.2 U20.114(IO_L65N_SCP2_0)
NetR66_2: R66.2 U20.112(IO_L66P_SCP1_0)
NetR67_2: R67.2 U20.111(IO_L66N_SCP0_0)
NetR78_1: R78.1 U20.144(IO_L1P_HSWAPEN_0)
NetR79_1: R79.1 U22.20(Y5)
NetR85_1: R85.1 U22.19(Y4)
NetR92_1: R92.1 U22.16(Y3)
NetR93_2: R93.2 R95.2 R97.2 U22.5(CLK_IN0)
NetR94_2: R94.2 U20.98(IO_L34P_1)
NetR99_2: R99.2 U20.97(IO_L34N_1)
NetR102_1: R102.1 U22.15(Y2)
NetR105_2: R105.2 U20.95(IO_L40P_GCLK11_1)
NetR106_2: R106.2 U20.94(IO_L40N_GCLK10_1)
NetR109_1: R109.1 U22.12(Y1)
NetR112_2: R112.2 U20.92(IO_L41N_GCLK8_1)
NetR119_2: R119.2 U20.85(IO_L43P_GCLK5_1)
NetR120_2: R120.2 U20.88(IO_L42P_GCLK7_1)
NetR126_1: R126.1 U22.11(Y0)
NetR128_2: R128.2 U20.62(IO_L12P_D1_MISO2_2) U27.3(~{W}/VPP/DQ2)
NetR129_1: R129.1 R134.2 R154.2 U27.6(C)
NetR133_1: R133.1 U29.8(Y3)
NetR136_1: R136.1 U29.4(VCTRL)
NetR141_1: R141.1 U27.2(DQ1)
NetR141_2: R141.2 U20.65(IO_L3P_D0_DIN_MISO_MISO1_2)
NetR146_1: R146.1 U20.51(IO_L31P_GCLK31_D14_2)
NetR146_2: R146.2 U33.1(OUT)
NetR147_1: R147.1 U29.11(Y1)
NetR148_1: R148.1 U20.39(IO_L65P_INIT_B_2)
NetR152_1: R152.1 U29.2(S0)
NetR154_1: R154.1 U20.70(IO_L1P_CCLK_2)
NetR155_1: R155.1 U27.5(DQ0)
NetR155_2: R155.2 U20.64(IO_L3N_MOSI_CSI_B_MISO0_2)
NetR171_1: R171.1 S2.1(A1) U20.102(IO_L32P_1)
NetR171_3: R171.3 S2.2(A2) U20.101(IO_L32N_1)
NetR171_5: R171.5 S2.3(A3) U20.100(IO_L33P_1)
NetR171_7: R171.7 S2.4(A4) U20.99(IO_L33N_1)
NetR174_1: R174.1 U35.2(SO)
NetR185_2: R185.2 U20.83(IO_L45P_1)
NetR187_1: R187.1 U20.58(IO_L14P_D11_2) U29.13(SDA/S1)
NetR188_1: R188.1 U20.59(IO_L13N_D10_2) U29.12(SCL/S2)
NetR189_1: R189.1 U29.9(Y2)
NetR195_2: R195.2 U20.61(IO_L12N_D2_MISO3_2) U27.7(~{Hold/DQ3})
NetR202_2: R202.2 U33.6(~{PDN})

Not connected (* = marked no-connect by the designer): U7 1(DCD) 2(RI) 10(NC) 12(SUSPEND) 13(NC) 14(NC) 15(NC) 16(NC) 17(NC) 18(NC) 19(NC) 20(NC) 21(NC) 22(NC) 23(CTS) 24(RTS) 27(DSR) 28(DTR); U20 44(IO_L62P_D5_2) 50(IO_L31N_GCLK30_D15_2) 57(IO_L14N_D12_2) 66(IO_L2N_CMPMOSI_2) 67(IO_L2P_CMPCLK_2) 74(IO_L74N_DOUT_BUSY_1) 75(IO_L74P_AWAKE_1) 78(IO_L47N_1) 79(IO_L47P_1) 93(IO_L41P_GCLK9_IRDY1_1) 104(IO_L1N_VREF_1) 105(IO_L1P_1) 143(IO_L1N_VREF_0); U33 7(DNC) 8(DNC); U35 3(NC); U37 1(NC)*

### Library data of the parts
C15 C17 C88 C92 C99 C175 = GRM188R70J224KA88D: as C126 on sheet FPGA Power
C22 C83 C86 C96 C127 = C0603C475K9PACTU: as C104 on sheet FPGA Power
C42 C56 C60 C62 C69 C74 C82 = 06031C103KAT2A: CAP, CERM, 0.01uF, 100V, +/-10%, X7R, 0603; Manufacturer: AVX; Polarized: N; CompType: Capacitor; U/M: EA; Cap_F: 0.00000001; Tolerance_%: 10; ESR_Ohm: 0.098; Value1: 0.098 ohm; VDC_V: 100; TaMin_C: -55; TaMax_C: 125
C43 C45 C53 C54 C72 C73 C76 C77 = 06033C104JAT2A: CAP, CERM, 0.1uF, 25V, +/-5%, X7R, 0603; Manufacturer: AVX; Polarized: N; CompType: Capacitor; U/M: EA; Cap_F: 0.0000001; Tolerance_%: 5; ESR_Ohm: 0.05; Value1: 0.05 ohm; VDC_V: 25; TaMin_C: -55; TaMax_C: 125
C55 C65 C106 C107 = 06035A270JAT2A: CAP, CERM, 27pF, 50V, +/-5%, C0G/NP0, 0603; Manufacturer: AVX; Polarized: N; CompType: Capacitor; U/M: EA; Cap_F: 0.000000000027; Tolerance_%: 5; ESR_Ohm: 0.232; Value1: 0.232 ohm; VDC_V: 50; TaMin_C: -55; TaMax_C: 125
C63 = C1608X5R1C105K: CAP, CERM, 1uF, 16V, +/-10%, X5R, 0603; Manufacturer: TDK; Polarized: N; CompType: Capacitor; U/M: EA; Cap_F: 0.000001; Tolerance_%: 10; ESR_Ohm: 0.0057; Value1: 0.0057 ohm; VDC_V: 16; TaMin_C: -55; TaMax_C: 85
C66 C178 = 0603YC104JAT2A: CAP, CERM, 0.1uF, 16V, +/-5%, X7R, 0603; Manufacturer: AVX; Polarized: N; CompType: Capacitor; U/M: EA; Cap_F: 0.0000001; Tolerance_%: 5; ESR_Ohm: 0.039; Value1: 0.039 ohm; VDC_V: 16; TaMin_C: -55; TaMax_C: 125
D1 D2 = PESD1LIN,115: Diode, TVS, Bi, 15V, 160W, SOD-323; Manufacturer: NXP Semiconductor; U/M: EA; Power_W: 160; Vr_V: 15
D3 = LED_LG L29K-G2J1-24-Z: as D9 on sheet FPGA Power
FB2 FB3 FB5 = MMZ1608B102C: FERRITE CHIP 1000 OHM 300MA 0603; Manufacturer: TDK Corporation; CompType: Ferrite Bead
J3 = CONN_USB_SD-47590-001: Connector, USB Micro, Type AB; Manufacturer: Molex; PartNumber: 47590-0001; Area: 63.60 mm
J14 = 142-0711-201: Connector, SMA Jack, Vertical, Gold, SMD; Manufacturer: Emerson Network Power; SymbolCreator: a0412235; U/M: EA
R9 R22 R79 R85 R92 R102 R109 R126 R130 R158 = CRCW06030000Z0EA: as R192 on sheet FPGA Power
R29 R78 R127 R136 R148 R152 R166 R187 R188 R202 = CRCW06034K87FKEA: as R144 on sheet FPGA Power
R30 = CRCW0603300RJNEA: RES, 300 ohm, 5%, 0.1W, 0603; Manufacturer: Vishay-Dale; CompType: Resistor; Value_Code: 300R; Tolerance_%: 5; Power_W: 0.1; VDC_V: 75; TempCo: 200 ppm/C; EIA_Code: E24; U/M: EA
R44-R67 R94 R99 R105 R106 R112 R119 R120 R133 R141 R146 R147 R154 R155 R174 R185 R189 = CRCW040222R0JNED: as R175 on sheet FPGA Power
R75 R76 R81 R82 R89 R90 R100 R101 R110 R111 R113-R115 R124 R125 R129 R134 = CRCW0603100RJNEA: RES, 100 ohm, 5%, 0.1W, 0603; Manufacturer: Vishay-Dale; CompType: Resistor; Value_Code: 100R; Tolerance_%: 5; Power_W: 0.1; VDC_V: 75; TempCo: 200 ppm/C; EIA_Code: E24; U/M: EA
R86 R88 R201 R203 R207 R208 = RC0603FR-074K7L: RES, 4.70k ohm, 1%, 0.1W, 0603; Manufacturer: Yageo America; CompType: Resistor; Res_ohm: 4700; Value_Code: 4k70; Tolerance_%: 1; Power_W: 0.1; VDC_V: 150; TempCo: 200 ppm/C; U/M: EA
R93 R95 R97 R104 R116 = CRCW04020000Z0ED: RES, 0 ohm, 5%, 0.063W, 0402; Manufacturer: Vishay-Dale; CompType: Resistor; Value_Code: 0000; Tolerance_%: 5; Power_W: 0.063; VDC_V: 50; TempCo: 200 ppm/C; EIA_Code: E24; U/M: EA
R103 R121 = CRCW060310K0JNEA: RES, 10k ohm, 5%, 0.1W, 0603; Manufacturer: Vishay-Dale; CompType: Resistor; Res_ohm: 10000; Value_Code: 10k0; Tolerance_%: 5; Power_W: 0.1; VDC_V: 75; TempCo: 200 ppm/C; EIA_Code: E24; U/M: EA
R128 R195 = CRCW0603100KFKEA: RES, 100k ohm, 1%, 0.1W, 0603; Manufacturer: Vishay-Dale; CompType: Resistor; Res_ohm: 100000; Tolerance_%: 1; Power_W: 0.1; VDC_V: 75; TempCo: 100 ppm/C; EIA_Code: E96; U/M: EA
R171 = R-ACAS0612_SERIES: as R167 on sheet FPGA Power
R194 = RC0603JR-0710KL: RES, 10k ohm, 5%, 0.1W, 0603; Manufacturer: Yageo America; CompType: Resistor; Res_ohm: 10000; Value_Code: 10k0; Tolerance_%: 5; Power_W: 0.1; VDC_V: 50; TempCo: 100 ppm/C; EIA_Code: E24; U/M: EA
S1 = 4-1437565-1: as S3 on sheet FPGA Power
S2 = 218-4LPST: Switch, Slide, SPST 4 poles, SMT; Manufacturer: CTS Electrocomponents; SymbolCreator: a0412235; VDC_V: 24; SwitchFunction: Off-On; PositionCount: 4; CurrentRating_mA: 25
U7 = CP2102: IC, Single Chip USB To UART Bridge; Manufacturer: Silicon Labratories; Area: 66564
U9 = ZEN056V130A24LS: Polyzen, 5.6V, PPTC/ZENER, SMD; Manufacturer: TE; Alternate Manufacturer: None
U20 = XC6SLX9-2TQG144I: as U20 on sheet FPGA Power
U22 = CDCE906PW: Programmable 3-PLL Clock Synthesizer / Multiplier / Divider; Manufacturer: TI; Alternate Manufacturer: None; SymbolCreator: x0120606; CompType: IC
U27 = N25Q128A13BSE40F: Single LVDS Transmitter; Manufacturer: Micron Technology; SymbolCreator: x0120606; CompType: IC
U29 = CDCE913PW: Programmable 1-PLL VCXO Clock Synthesizer With 1.8-V, 2.5-V, and 3.3-V Outputs, PW0014A; Alternate Manufacturer: None; Manufacturer: Texas Instruments; SymbolCreator: a0411947; CompType: IC; U/M: EA
U33 = DS1088LU-XX: IC,  100MHz, EconOscillator, 2.7-3.6V, 8 uSOP; Manufacturer: Maxim; Area: 39750
U35 = 23LC512-I/SN: IC SRAM 512KBIT 20MHZ 8SOIC; Alternate Manufacturer: None; Manufacturer: Microchip Technology; SymbolCreator: x0120606
U37 = CAT24M01WI-GT3: IC EEPROM 1MBIT 1MHZ 8SOIC; Alternate Manufacturer: None; Manufacturer: ON Semiconductor; SymbolCreator: x0120606
Y1 Y2 = 7B-10.000MEEQ-T: Crystal, 10.000MHz, 10pF, SMD; Manufacturer: TXC Corporation; SymbolCreator: a0412235; U/M: EA; TaMin_C: -20; TaMax_C: 70; Frequency Stability: ±10ppm

## Sheet DAC.SchDoc: DAC
size 431 x 279 mm; Date: Not shown in title block; ApprovedBy: Not shown in title block; CheckedBy: Not shown in title block; Author: Not shown in title block; CompanyName: Not shown in title block; Engineer: Not shown in title block; Organization: Not shown in title block; Address1: Not shown in title block; Address2: Not shown in title block; Address3: Not shown in title block; Address4: Not shown in title block; DocumentNumber: 8; Revision: Use project parameter SCH_Rev; SheetNumber: 8; SheetTotal: 9; PageSetup: Record=PageOptions|CenterHorizontal=True|CenterVertical=True|PrintScale=1.00|XCorrection=1.00|YCorrection=1.00|PrintKind=0|BorderSize=5000000|LeftOffset=0|BottomOffset=0|Orientation=2|PaperLength=1000|PaperWidth=1000|Scale=100|PaperSource=15|PrintQuality=600|MediaType=1|DitherType=10|PaperKind=Letter|PrintScaleMode=1
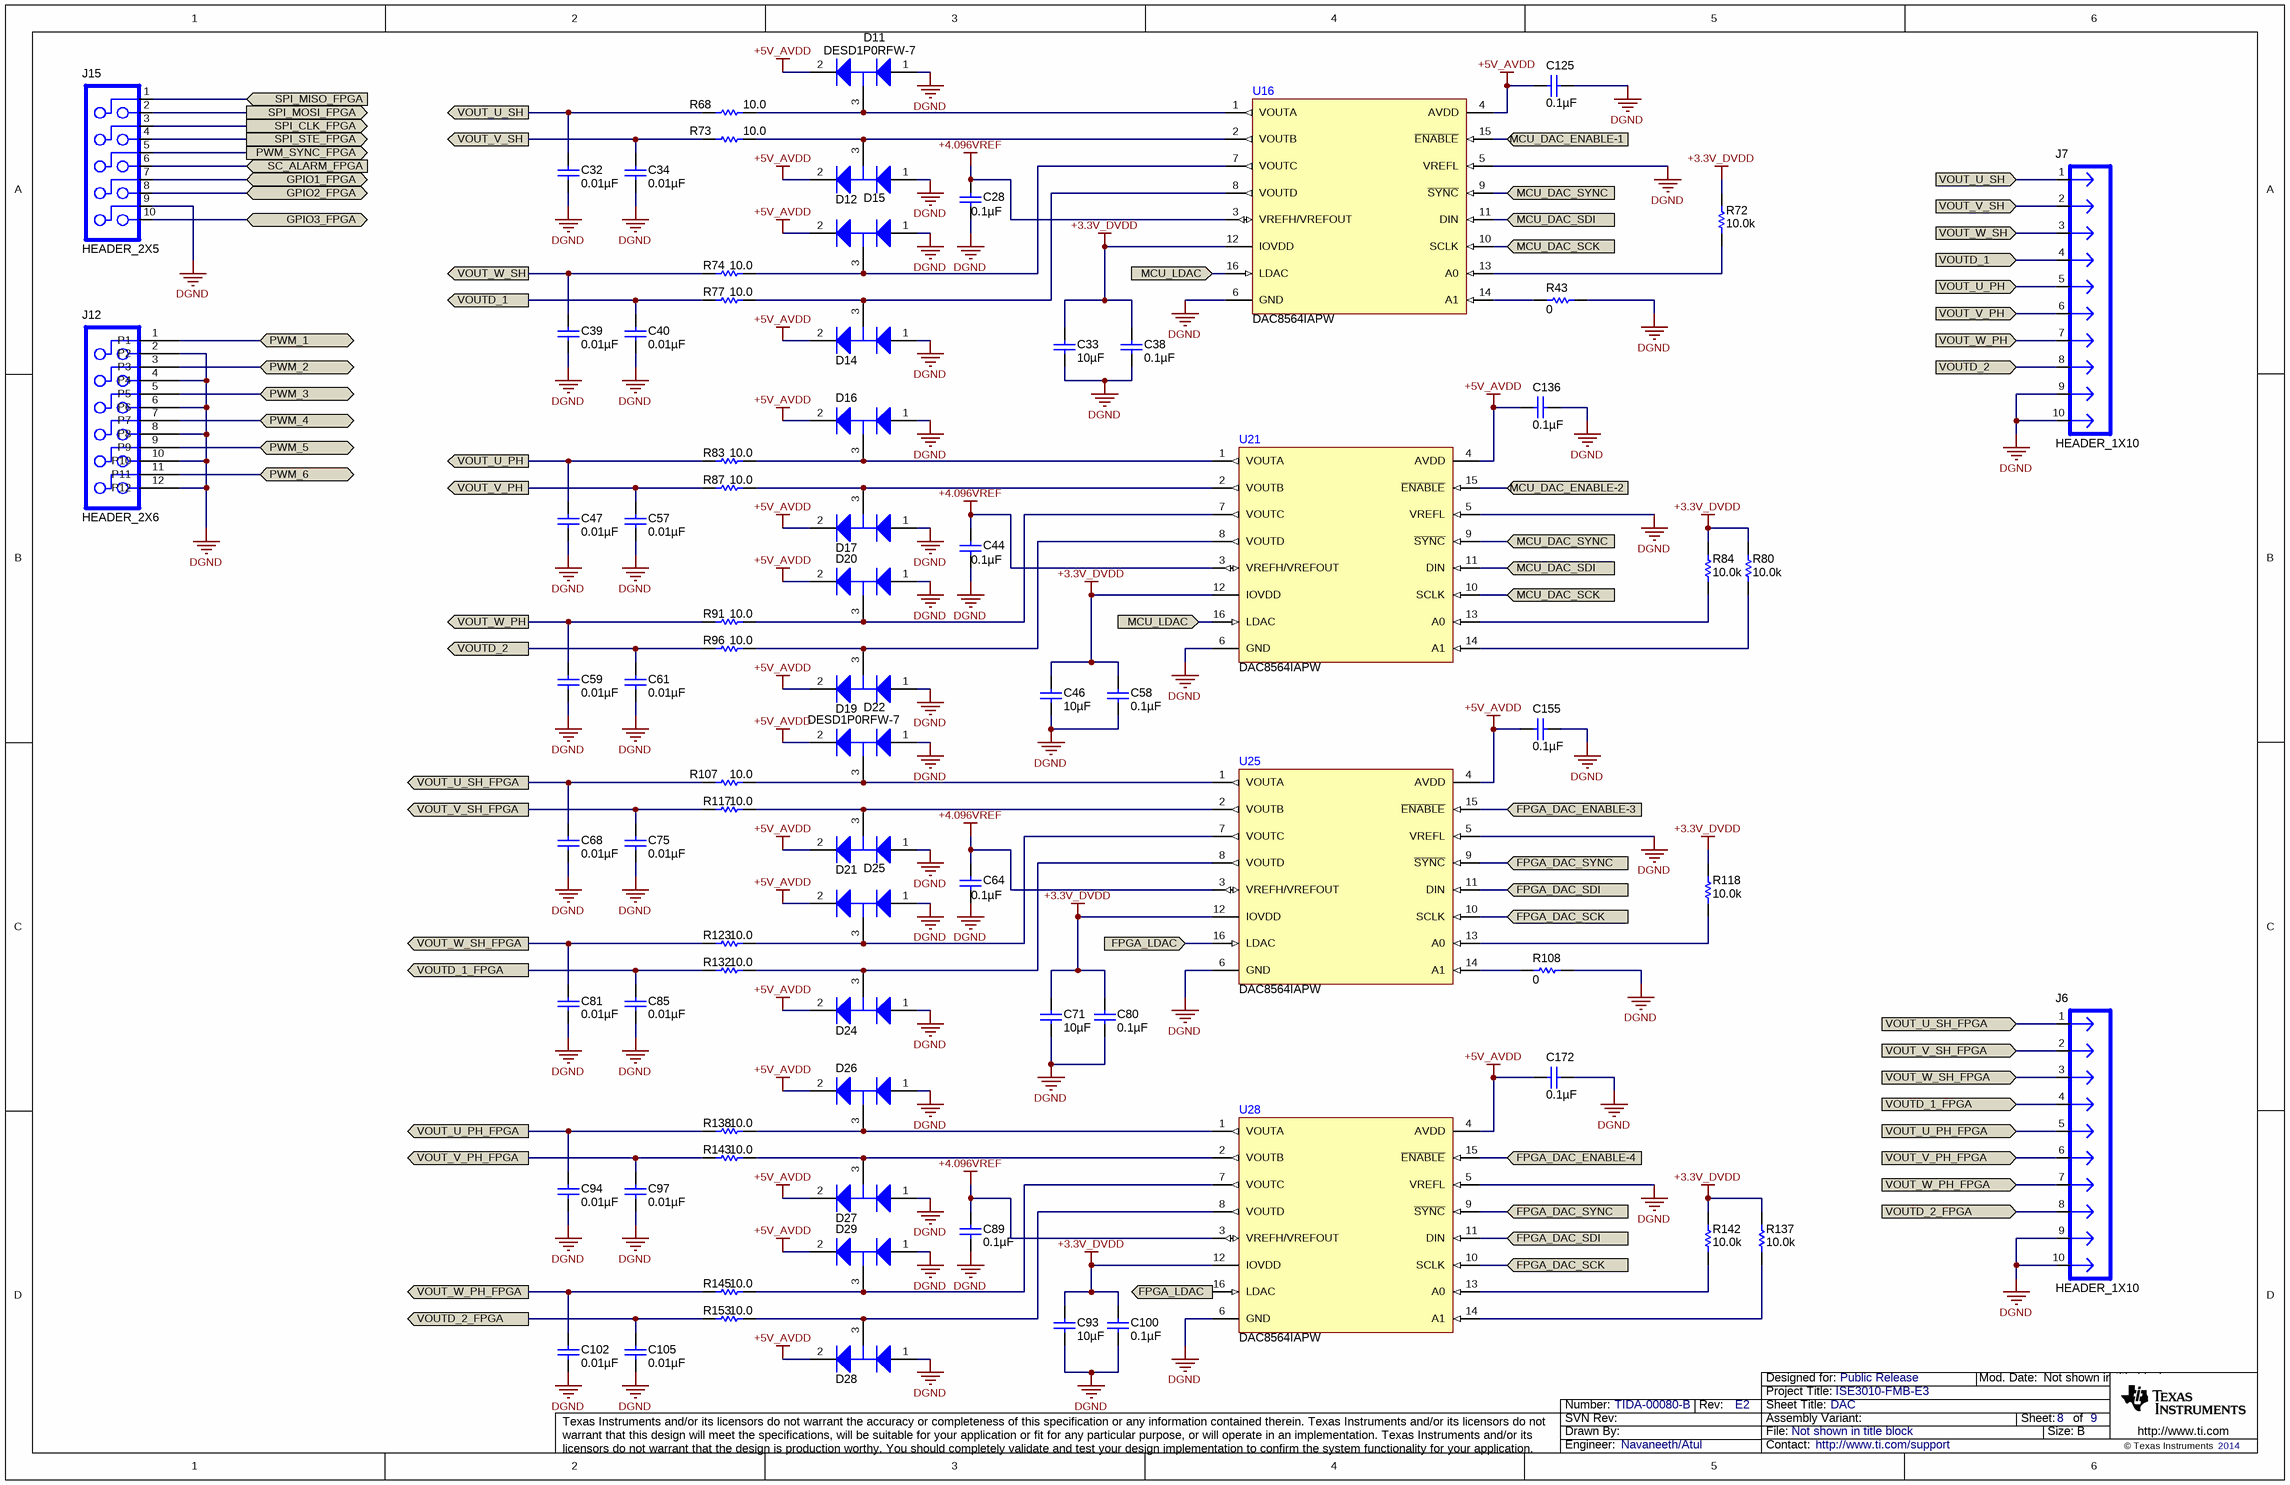
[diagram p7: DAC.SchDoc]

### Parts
C28  ValueDisplayed: 0.1µF  [0603]
C32  ValueDisplayed: 0.01µF  [0603]
C33  ValueDisplayed: 10µF  [1210]
C34  ValueDisplayed: 0.01µF  [0603]
C38  ValueDisplayed: 0.1µF  [0603]
C39  ValueDisplayed: 0.01µF  [0603]
C40  ValueDisplayed: 0.01µF  [0603]
C44  ValueDisplayed: 0.1µF  [0603]
C46  ValueDisplayed: 10µF  [1210]
C47  ValueDisplayed: 0.01µF  [0603]
C57  ValueDisplayed: 0.01µF  [0603]
C58  ValueDisplayed: 0.1µF  [0603]
C59  ValueDisplayed: 0.01µF  [0603]
C61  ValueDisplayed: 0.01µF  [0603]
C64  ValueDisplayed: 0.1µF  [0603]
C68  ValueDisplayed: 0.01µF  [0603]
C71  ValueDisplayed: 10µF  [1210]
C75  ValueDisplayed: 0.01µF  [0603]
C80  ValueDisplayed: 0.1µF  [0603]
C81  ValueDisplayed: 0.01µF  [0603]
C85  ValueDisplayed: 0.01µF  [0603]
C89  ValueDisplayed: 0.1µF  [0603]
C93  ValueDisplayed: 10µF  [1210]
C94  ValueDisplayed: 0.01µF  [0603]
C97  ValueDisplayed: 0.01µF  [0603]
C100  ValueDisplayed: 0.1µF  [0603]
C102  ValueDisplayed: 0.01µF  [0603]
C105  ValueDisplayed: 0.01µF  [0603]
C125  ValueDisplayed: 0.1µF  [0603]
C136  ValueDisplayed: 0.1µF  [0603]
C155  ValueDisplayed: 0.1µF  [0603]
C172  ValueDisplayed: 0.1µF  [0603]
D11  PartNumber: DESD1P0RFW-7  [SOT-323]
D12  (no value)  [SOT-323]
D14  (no value)  [SOT-323]
D15  (no value)  [SOT-323]
D16  (no value)  [SOT-323]
D17  (no value)  [SOT-323]
D19  (no value)  [SOT-323]
D20  (no value)  [SOT-323]
D21  (no value)  [SOT-323]
D22  PartNumber: DESD1P0RFW-7  [SOT-323]
D24  (no value)  [SOT-323]
D25  (no value)  [SOT-323]
D26  (no value)  [SOT-323]
D27  (no value)  [SOT-323]
D28  (no value)  [SOT-323]
D29  (no value)  [SOT-323]
J6  HEADER_1X10  [HDR100_1X10]
J7  HEADER_1X10  [HDR100_1X10]
J12  HEADER_2X6  [HEADER_2X6]
J15  HEADER_2X5  [HEADER_2X5]
R43  value 0  [0603]  (hidden comment: CRCW06030000Z0EA)
R68  value 10.0  [0603]
R72  value 10.0k  [0603]  (hidden comment: CRCW060310K0FKEA)
R73  value 10.0  [0603]
R74  value 10.0  [0603]
R77  value 10.0  [0603]
R80  value 10.0k  [0603]  (hidden comment: CRCW060310K0FKEA)
R83  value 10.0  [0603]
R84  value 10.0k  [0603]  (hidden comment: CRCW060310K0FKEA)
R87  value 10.0  [0603]
R91  value 10.0  [0603]
R96  value 10.0  [0603]
R107  value 10.0  [0603]
R108  value 0  [0603]  (hidden comment: CRCW06030000Z0EA)
R117  value 10.0  [0603]
R118  value 10.0k  [0603]  (hidden comment: CRCW060310K0FKEA)
R123  value 10.0  [0603]
R132  value 10.0  [0603]
R137  value 10.0k  [0603]  (hidden comment: CRCW060310K0FKEA)
R138  value 10.0  [0603]
R142  value 10.0k  [0603]  (hidden comment: CRCW060310K0FKEA)
R143  value 10.0  [0603]
R145  value 10.0  [0603]
R153  value 10.0  [0603]
U16  DAC8564IAPW  [PW0016A_N]
U21  DAC8564IAPW  [PW0016A_N]
U25  DAC8564IAPW  [PW0016A_N]
U28  DAC8564IAPW  [PW0016A_N]

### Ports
FPGA_DAC_ENABLE-3 (in), FPGA_DAC_ENABLE-4 (in), FPGA_DAC_SCK (in), FPGA_DAC_SDI (in), FPGA_DAC_SYNC (in), FPGA_LDAC (in), GPIO1_FPGA (bidir), GPIO2_FPGA (bidir), GPIO3_FPGA (bidir), MCU_DAC_ENABLE-1, MCU_DAC_ENABLE-2, MCU_DAC_SCK, MCU_DAC_SDI, MCU_DAC_SYNC, MCU_LDAC (in), PWM_1 (bidir), PWM_2 (bidir), PWM_3 (bidir), PWM_4 (bidir), PWM_5 (bidir), PWM_6 (bidir), PWM_SYNC_FPGA, SC_ALARM_FPGA (in), SPI_CLK_FPGA, SPI_MISO_FPGA (in), SPI_MOSI_FPGA, SPI_STE_FPGA, VOUT_U_PH, VOUT_U_PH (in), VOUT_U_PH_FPGA, VOUT_U_PH_FPGA (in), VOUT_U_SH, VOUT_U_SH (in), VOUT_U_SH_FPGA, VOUT_U_SH_FPGA (in), VOUT_V_PH, VOUT_V_PH (in), VOUT_V_PH_FPGA, VOUT_V_PH_FPGA (in), VOUT_V_SH, VOUT_V_SH (in), VOUT_V_SH_FPGA, VOUT_V_SH_FPGA (in), VOUT_W_PH, VOUT_W_PH (in), VOUT_W_PH_FPGA, VOUT_W_PH_FPGA (in), VOUT_W_SH, VOUT_W_SH (in), VOUT_W_SH_FPGA, VOUT_W_SH_FPGA (in), VOUTD_1, VOUTD_1 (in), VOUTD_1_FPGA, VOUTD_1_FPGA (in), VOUTD_2, VOUTD_2 (in), VOUTD_2_FPGA, VOUTD_2_FPGA (in)

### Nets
+3.3V_DVDD: C33.1 C38.2 C46.1 C58.2 C71.1 C80.2 C93.1 C100.2 R72.2 R80.2 R84.2 R118.2 R137.2 R142.2 U16.12(IOVDD) U21.12(IOVDD) U25.12(IOVDD) U28.12(IOVDD)
+4.096VREF: C28.2 C44.2 C64.2 C89.2 U16.3(VREFH/VREFOUT) U21.3(VREFH/VREFOUT) U25.3(VREFH/VREFOUT) U28.3(VREFH/VREFOUT)
+5V_AVDD: C125.2 C136.2 C155.2 C172.2 D11.2(K) D12.2(K) D14.2(K) D15.2(K) D16.2(K) D17.2(K) D19.2(K) D20.2(K) D21.2(K) D22.2(K) D24.2(K) D25.2(K) D26.2(K) D27.2(K) D28.2(K) D29.2(K) U16.4(AVDD) U21.4(AVDD) U25.4(AVDD) U28.4(AVDD)
DGND: C28.1 C32.1 C33.2 C34.1 C38.1 C39.1 C40.1 C44.1 C46.2 C47.1 C57.1 C58.1 C59.1 C61.1 C64.1 C68.1 C71.2 C75.1 C80.1 C81.1 C85.1 C89.1 C93.2 C94.1 C97.1 C100.1 C102.1 C105.1 C125.1 C136.1 C155.1 C172.1 D11.1(A) D12.1(A) D14.1(A) D15.1(A) D16.1(A) D17.1(A) D19.1(A) D20.1(A) D21.1(A) D22.1(A) D24.1(A) D25.1(A) D26.1(A) D27.1(A) D28.1(A) D29.1(A) J6.9 J6.10 J7.9 J7.10 J12.2(P2) J12.4(P4) J12.6(P6) J12.8(P8) J12.10(P10) J12.12(P12) J15.9(P9) R43.2 R108.2 U16.5(VREFL) U16.6(GND) U21.5(VREFL) U21.6(GND) U25.5(VREFL) U25.6(GND) U28.5(VREFL) U28.6(GND)
FPGA_DAC_ENABLE-3: U25.15(~{ENABLE}) ; port FPGA_DAC_ENABLE-3
FPGA_DAC_ENABLE-4: U28.15(~{ENABLE}) ; port FPGA_DAC_ENABLE-4
FPGA_DAC_SCK: U25.10(SCLK) U28.10(SCLK) ; port FPGA_DAC_SCK
FPGA_DAC_SDI: U25.11(DIN) U28.11(DIN) ; port FPGA_DAC_SDI
FPGA_DAC_SYNC: U25.9(~{SYNC}) U28.9(~{SYNC}) ; port FPGA_DAC_SYNC
FPGA_LDAC: U25.16(LDAC) U28.16(LDAC) ; port FPGA_LDAC
GPIO1_FPGA: J15.7(P7) ; port GPIO1_FPGA
GPIO2_FPGA: J15.8(P8) ; port GPIO2_FPGA
GPIO3_FPGA: J15.10(P10) ; port GPIO3_FPGA
MCU_DAC_ENABLE-1: U16.15(~{ENABLE}) ; port MCU_DAC_ENABLE-1
MCU_DAC_ENABLE-2: U21.15(~{ENABLE}) ; port MCU_DAC_ENABLE-2
MCU_DAC_SCK: U16.10(SCLK) U21.10(SCLK) ; port MCU_DAC_SCK
MCU_DAC_SDI: U16.11(DIN) U21.11(DIN) ; port MCU_DAC_SDI
MCU_DAC_SYNC: U16.9(~{SYNC}) U21.9(~{SYNC}) ; port MCU_DAC_SYNC
MCU_LDAC: U16.16(LDAC) U21.16(LDAC) ; port MCU_LDAC
PWM_1: J12.1(P1) ; port PWM_1
PWM_2: J12.3(P3) ; port PWM_2
PWM_3: J12.5(P5) ; port PWM_3
PWM_4: J12.7(P7) ; port PWM_4
PWM_5: J12.9(P9) ; port PWM_5
PWM_6: J12.11(P11) ; port PWM_6
PWM_SYNC_FPGA: J15.5(P5) ; port PWM_SYNC_FPGA
SC_ALARM_FPGA: J15.6(P6) ; port SC_ALARM_FPGA
SPI_CLK_FPGA: J15.3(P3) ; port SPI_CLK_FPGA
SPI_MISO_FPGA: J15.1(P1) ; port SPI_MISO_FPGA
SPI_MOSI_FPGA: J15.2(P2) ; port SPI_MOSI_FPGA
SPI_STE_FPGA: J15.4(P4) ; port SPI_STE_FPGA
VOUT_U_PH: C47.2 J7.5 R83.1 ; port VOUT_U_PH
VOUT_U_PH_FPGA: C94.2 J6.5 R138.1 ; port VOUT_U_PH_FPGA
VOUT_U_SH: C32.2 J7.1 R68.1 ; port VOUT_U_SH
VOUT_U_SH_FPGA: C68.2 J6.1 R107.1 ; port VOUT_U_SH_FPGA
VOUT_V_PH: C57.2 J7.6 R87.1 ; port VOUT_V_PH
VOUT_V_PH_FPGA: C97.2 J6.6 R143.1 ; port VOUT_V_PH_FPGA
VOUT_V_SH: C34.2 J7.2 R73.1 ; port VOUT_V_SH
VOUT_V_SH_FPGA: C75.2 J6.2 R117.1 ; port VOUT_V_SH_FPGA
VOUT_W_PH: C59.2 J7.7 R91.1 ; port VOUT_W_PH
VOUT_W_PH_FPGA: C102.2 J6.7 R145.1 ; port VOUT_W_PH_FPGA
VOUT_W_SH: C39.2 J7.3 R74.1 ; port VOUT_W_SH
VOUT_W_SH_FPGA: C81.2 J6.3 R123.1 ; port VOUT_W_SH_FPGA
VOUTD_1: C40.2 J7.4 R77.1 ; port VOUTD_1
VOUTD_1_FPGA: C85.2 J6.4 R132.1 ; port VOUTD_1_FPGA
VOUTD_2: C61.2 J7.8 R96.1 ; port VOUTD_2
VOUTD_2_FPGA: C105.2 J6.8 R153.1 ; port VOUTD_2_FPGA
NetD11_3: D11.3(C) R68.2 U16.1(VOUTA)
NetD12_3: D12.3(C) R73.2 U16.2(VOUTB)
NetD14_3: D14.3(C) R77.2 U16.8(VOUTD)
NetD15_3: D15.3(C) R74.2 U16.7(VOUTC)
NetD16_3: D16.3(C) R83.2 U21.1(VOUTA)
NetD17_3: D17.3(C) R87.2 U21.2(VOUTB)
NetD19_3: D19.3(C) R96.2 U21.8(VOUTD)
NetD20_3: D20.3(C) R91.2 U21.7(VOUTC)
NetD21_3: D21.3(C) R117.2 U25.2(VOUTB)
NetD22_3: D22.3(C) R107.2 U25.1(VOUTA)
NetD24_3: D24.3(C) R132.2 U25.8(VOUTD)
NetD25_3: D25.3(C) R123.2 U25.7(VOUTC)
NetD26_3: D26.3(C) R138.2 U28.1(VOUTA)
NetD27_3: D27.3(C) R143.2 U28.2(VOUTB)
NetD28_3: D28.3(C) R153.2 U28.8(VOUTD)
NetD29_3: D29.3(C) R145.2 U28.7(VOUTC)
NetR43_1: R43.1 U16.14(A1)
NetR72_1: R72.1 U16.13(A0)
NetR80_1: R80.1 U21.14(A1)
NetR84_1: R84.1 U21.13(A0)
NetR108_1: R108.1 U25.14(A1)
NetR118_1: R118.1 U25.13(A0)
NetR137_1: R137.1 U28.14(A1)
NetR142_1: R142.1 U28.13(A0)

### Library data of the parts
C28 C38 C44 C58 C64 C80 C89 C100 C125 C136 C155 C172 = C0603C104K5RACTU: CAP, CERM, 0.1uF, 50V, +/-10%, X7R, 0603; Manufacturer: Kemet; Polarized: N; CompType: Capacitor; U/M: EA; Cap_F: 0.0000001; Tolerance_%: 10; Value1: Unknown; VDC_V: 50; TaMin_C: -55; TaMax_C: 125
C32 C34 C39 C40 C47 C57 C59 C61 C68 C75 C81 C85 C94 C97 C102 C105 = 06031C103JAT2A: CAP, CERM, 0.01uF, 100V, +/-5%, X7R, 0603; Manufacturer: AVX; Polarized: N; CompType: Capacitor; U/M: EA; Cap_F: 0.00000001; Tolerance_%: 5; ESR_Ohm: 0.098; Value1: 0.098 ohm; VDC_V: 100; TaMin_C: -55; TaMax_C: 125
C33 C46 C71 C93 = GMK325AB7106MM-T: CAP, CERM, 10uF, 35V, +/-20%, X7R, 1210; Manufacturer: Taiyo Yuden; Polarized: N; CompType: Capacitor; U/M: EA; Cap_F: 0.00001; Tolerance_%: 20; Value1: Unknown; VDC_V: 35; TaMin_C: -55; TaMax_C: 125
D11 D22 = BAV99WT1G: Diode, P-N, 70V, 0.2A, SOT-323; Manufacturer: Diodes Inc; Value: DNP
D12 D14-D17 D19-D21 D24-D29 = BAV99WT1G: Diode, P-N, 70V, 0.2A, SOT-323; PartNumber: DESD1P0RFW-7; Manufacturer: Diodes Inc; Value: DNP
J6 J7 = HEADER_1X10: Header,  Male 10-pin, 100mil spacing,; Manufacturer: Sullins; PartNumber: PEC10SAAN; area: 133900; Value: PEC10SAAN
J12 = HEADER_2X6: Header, Male 2x6 pin, 100mil spacing; Manufacturer: Sullins; PartNumber: PEC06DAAN; area: 144900; Value: PEC06DAAN
J15 = HEADER_2X5: Header, Male 2x5-pin, 100mil spacing; Manufacturer: Sullins; PartNumber: PEC05DAAN; area: 100000; Value: PEC05DAAN
R43 R108 = CRCW06030000Z0EA: as R192 on sheet FPGA Power
R68 R73 R74 R77 R83 R87 R91 R96 R107 R117 R123 R132 R138 R143 R145 R153 = CRCW060310R0FKEA: RES, 10.0 ohm, 1%, 0.1W, 0603; Manufacturer: Vishay-Dale; CompType: Resistor; Res_ohm: 10; Value_Code: 10R0; Tolerance_%: 1; Power_W: 0.1; VDC_V: 75; TempCo: 100 ppm/C; EIA_Code: E96; U/M: EA
R72 R80 R84 R118 R137 R142 = CRCW060310K0FKEA: RES, 10.0k ohm, 1%, 0.1W, 0603; Manufacturer: Vishay-Dale; CompType: Resistor; Res_ohm: 10000; Value_Code: 10k0; Tolerance_%: 1; Power_W: 0.1; VDC_V: 75; TempCo: 100 ppm/C; EIA_Code: E96; U/M: EA
U16 U21 U25 U28 = DAC8564IAPW: 16-Bit, Quad Channel, Ultra-Low Glitch, Voltage Output DAC with 2.5V, 2ppm/°C Internal Reference, PW0016A; Alternate Manufacturer: None; Manufacturer: Texas Instruments; SymbolCreator: x0208326; CompType: IC; U/M: EA

## Sheet Hardware.SchDoc: Hardware - MIiscellaneous
size 431 x 279 mm; Date: Not shown in title block; ApprovedBy: Not shown in title block; CheckedBy: Not shown in title block; Author: Not shown in title block; CompanyName: Not shown in title block; Engineer: Not shown in title block; Organization: Not shown in title block; Address1: Not shown in title block; Address2: Not shown in title block; Address3: Not shown in title block; Address4: Not shown in title block; DocumentNumber: 9; Revision: Use project parameter SCH_Rev; SheetNumber: 9; SheetTotal: 9; PageSetup: Record=PageOptions|CenterHorizontal=True|CenterVertical=True|PrintScale=1.00|XCorrection=1.00|YCorrection=1.00|PrintKind=0|BorderSize=5000000|LeftOffset=0|BottomOffset=0|Orientation=2|PaperLength=1000|PaperWidth=1000|Scale=100|PaperSource=15|PrintQuality=600|MediaType=1|DitherType=10|PaperKind=Letter|PrintScaleMode=1
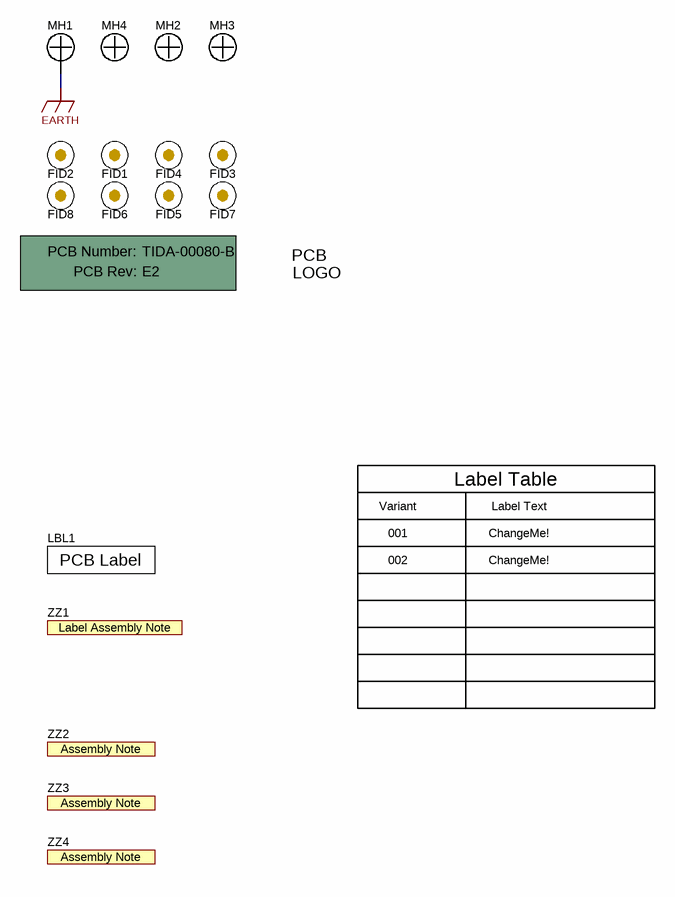
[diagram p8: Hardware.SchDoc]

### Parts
!PCB1  (no value)  (mechanical)
FID1  (no value)  [Fiducial10-20]
FID2  (no value)  [Fiducial10-20]
FID3  (no value)  [Fiducial10-20]
FID4  (no value)  [Fiducial10-20]
FID5  (no value)  [Fiducial10-20]
FID6  (no value)  [Fiducial10-20]
FID7  (no value)  [Fiducial10-20]
FID8  (no value)  [Fiducial10-20]
LBL1  (no value)  [Label_650x200]
Logo1  (no value)  [TI_Stacked_SolderMask_Small]  (no BOM)
MH1  (no value)  [MH3.2]
MH2  (no value)  [MH3.2_NPTH]
MH3  (no value)  [MH3.2_NPTH]
MH4  (no value)  [MH3.2_NPTH]
ZZ1  (no value)  [AssemblyNoteLabel]  (no BOM)
ZZ2  (no value)  [AssemblyNote]  (no BOM)
ZZ3  (no value)  [AssemblyNote]  (no BOM)
ZZ4  (no value)  [AssemblyNote]  (no BOM)

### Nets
EARTH: MH1.1

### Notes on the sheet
- Variant
- Label Table
- Label Text
- 001
- 002
- ChangeMe!

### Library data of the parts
!PCB1 = PCB: Printed Circuit Board; Manufacturer: Any; PartNumber: TIDA-00080-B; SymbolCreator: a0412235
FID1-FID8 = Fiducial: Fiducial mark.  There is nothing to buy or mount.; SymbolCreator: codlsc
LBL1 = THT-14-423-10: Thermal Transfer Printable Labels, 0.650" W x 0.200" H - 10,000 per roll; Manufacturer: Brady; SymbolCreator: a0412235; CompType: Label; Note: Size: 0.65" x 0.20 "
Logo1 = TI_Logo: Texas Instrument Corporate Signature; SymbolCreator: codlsc
MH1-MH4 = NY PMS 440 0025 PH: Mountin hole, NPTH Drill 3.2mm; CompType: Hardware
ZZ1 = AssemblyNoteLabel: This Assembly Note is for PCB labels only; SymbolCreator: a0412235
ZZ2 = AssemblyNote: These assemblies are ESD sensitive, ESD precautions shall be observed.; SymbolCreator: codlsc
ZZ3 = AssemblyNote: These assemblies must be clean and free from flux and all contaminants. Use of no clean flux is not acceptable.; SymbolCreator: codlsc
ZZ4 = AssemblyNote: These assemblies must comply with workmanship standards IPC-A-610 Class 2, unless otherwise specified.; SymbolCreator: codlsc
